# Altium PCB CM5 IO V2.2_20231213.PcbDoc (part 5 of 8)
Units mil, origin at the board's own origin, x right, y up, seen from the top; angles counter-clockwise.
Board outline 6299.61 x 3544.09 mil, 4 copper layers (Top, GND, Power, Bottom), stack 35.4 mil thick; 482 components, 404 nets, 1857 pads, 2731 vias.
Unrouted connection lines stored in the file: 1872.
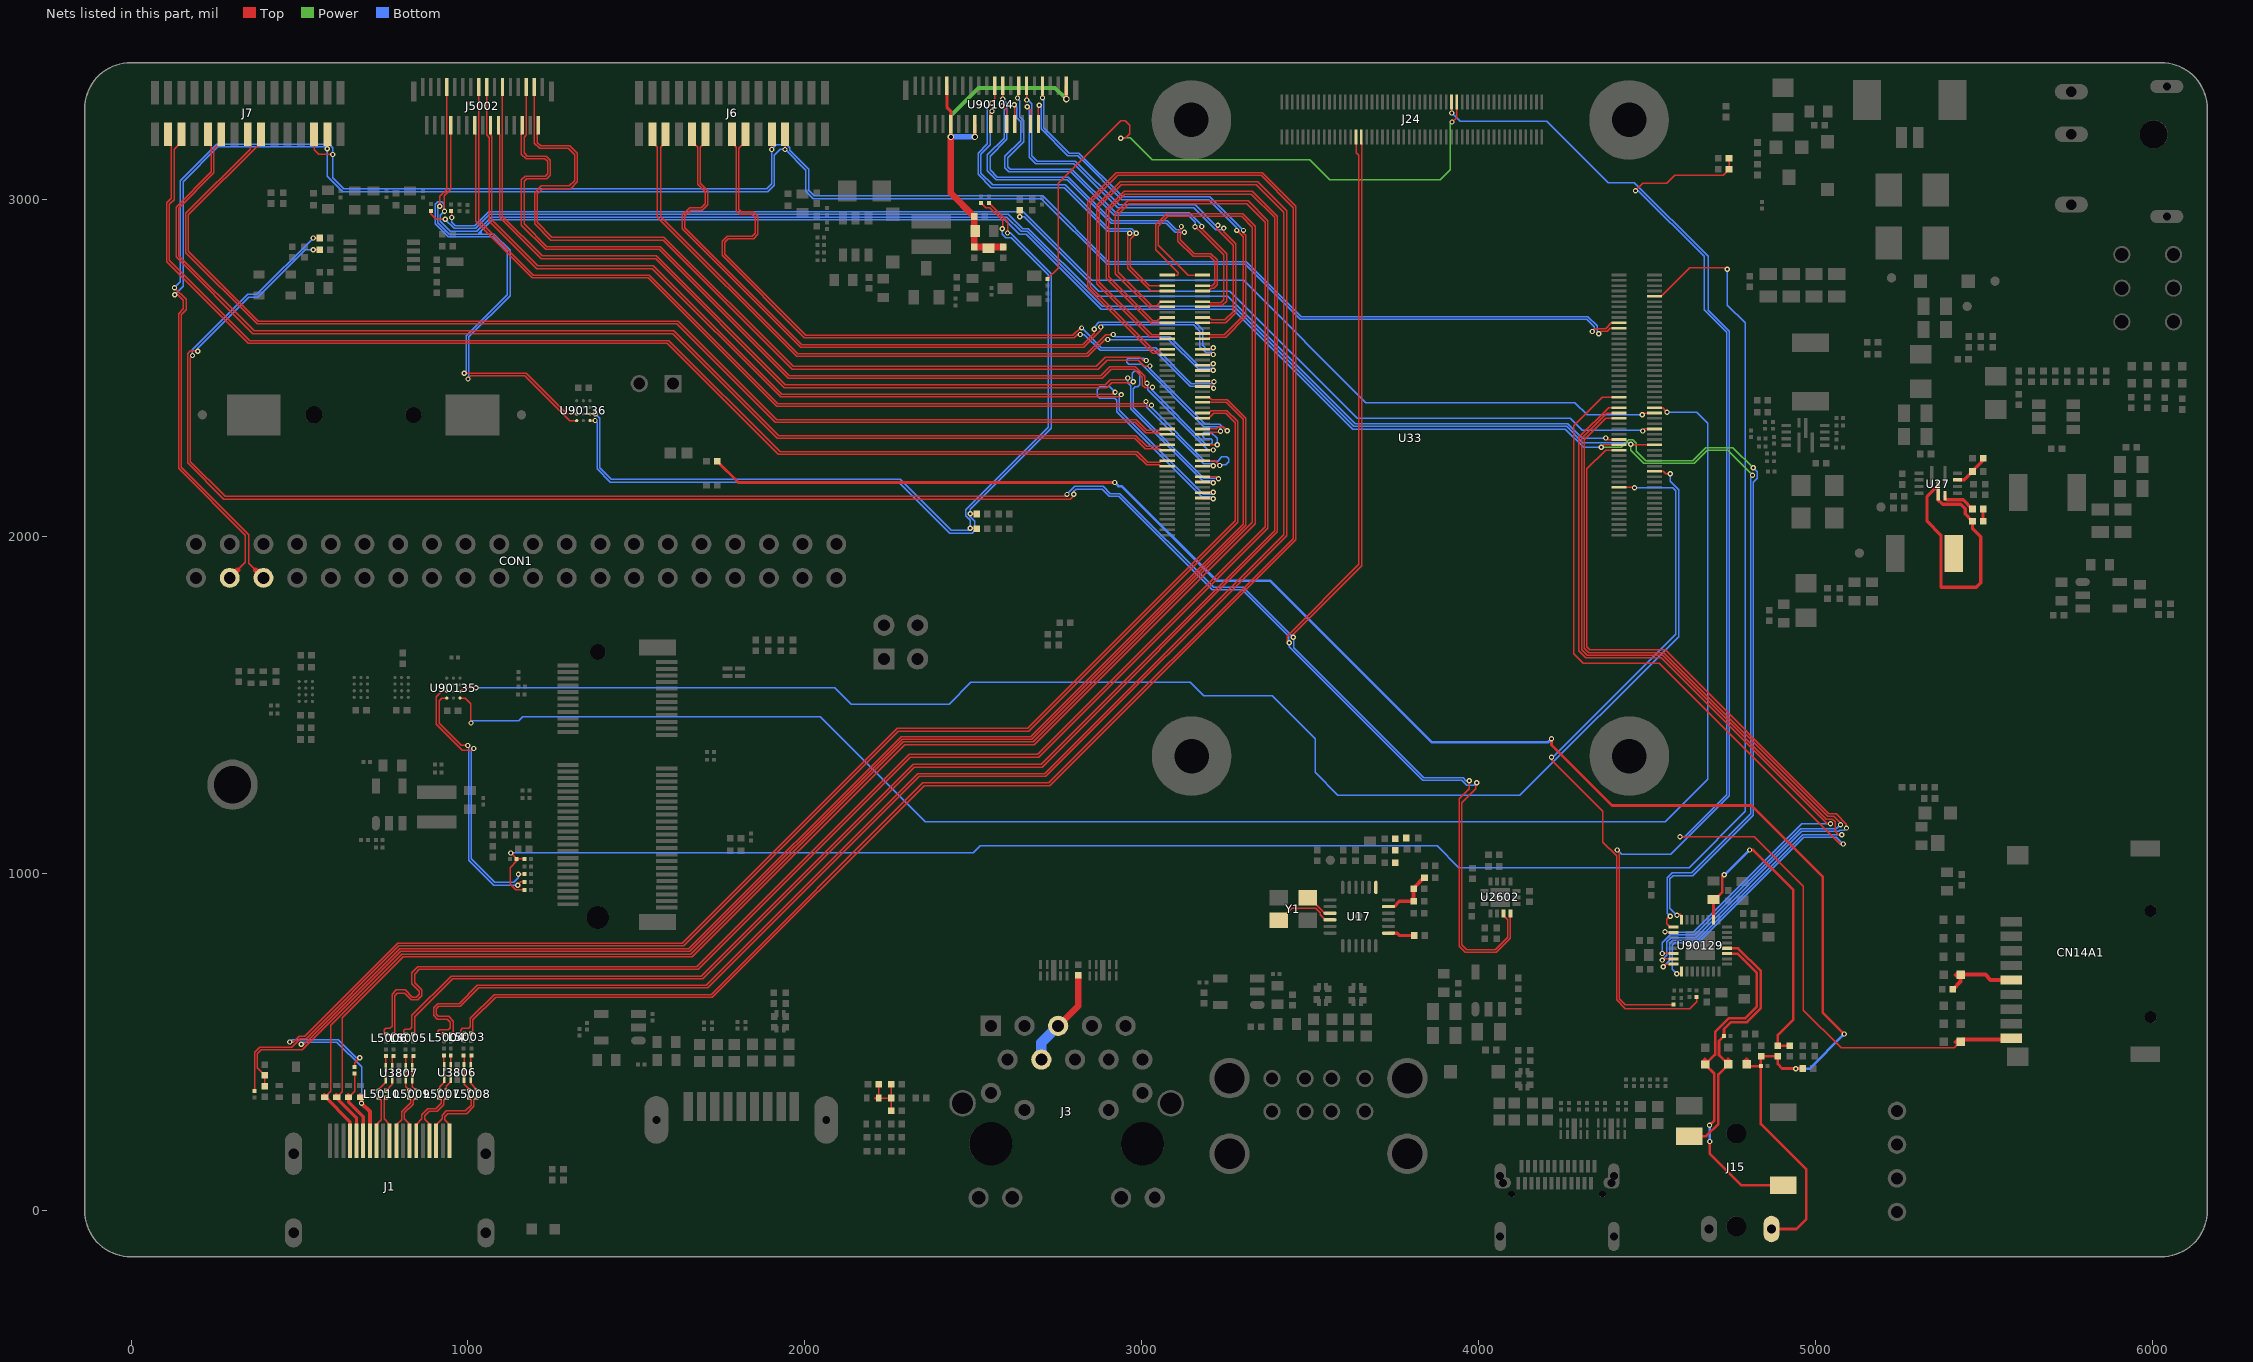
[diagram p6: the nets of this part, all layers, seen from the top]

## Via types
v1: diameter 15.75, hole 7.87, Top to Bottom, 2292 vias
v2: diameter 19.68, hole 11.81, Top to Bottom, 439 vias

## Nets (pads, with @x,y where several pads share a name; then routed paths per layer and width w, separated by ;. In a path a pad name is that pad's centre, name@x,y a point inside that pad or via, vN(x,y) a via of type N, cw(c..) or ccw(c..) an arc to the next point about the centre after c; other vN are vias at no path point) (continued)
HDMI0_SBDP: C90429.2 ED5.1 J1.14 | length 224.1
  Top w3.94: ED5.1@645.67,334.65 663.39,352.36 C90429.2@663.39,405.51
  Top w9.84: ED5.1@645.67,334.65 645.67,320.87 688.98,277.56 J1.14@688.98,206.69
HDMI0_TX0N: L5005.2 R957.1 U33.184 | length 5135.2
  Top w3.94: L5005.2@816.73,521.65 816.73,520.67 R957.1@814.96,520.67 810.04,525.59 810.04,533.46 813.98,537.4 827.76,537.4 833.66,543.31 833.66,577.76 950.79,694.88 1692.91,694.88 2320.87,1322.83 2700.51,1322.83 3393.7,2016.02 3393.7,2945.87 3324.8,3014.76 2949.32,3014.76 2901.57,2967.02 2901.57,2769.68 3032.48,2638.78 3045.28,2638.78 3055.51,2649.02 U33.184@3075.2,2649.02
HDMI0_TX0N_PORT: C90422.2 L5009.2 R95267.1 U3807.2 U3807.9 | length 110.3
  Top w3.94: C90422.2@814.96,457.68 814.96,444.39 U3807.2@814.96,423.72 U3807.9@814.96,389.28 814.96,366.93 L5009.2@826.57,355.31 826.57,355.02 825.34,353.79 825.34,354.33 R95267.1@824.8,354.33
HDMI0_TX0N_PORT_C: J1.9 L5009.3 R95267.2 | length 145.8
  Top w3.94: J1.9@787.41,206.69 787.41,252.96 803.15,268.7 803.15,292.32 829.72,318.9 829.72,330.51 L5009.3@826.57,333.66
HDMI0_TX0P: L5005.1 R956.1 U33.182 | length 5154.5
  Top w3.94: R956.1@837.6,520.67 837.01,520.67 837.01,520.08 835.63,521.46 L5005.1@835.63,521.65 841.54,527.56 841.54,573.82 954.72,687.01 1696.85,687.01 2324.8,1314.96 2703.79,1314.96 3401.57,2012.74 3401.57,2949.8 3327.76,3023.62 2947.04,3023.62 2893.7,2970.28 2893.7,2765.75 3028.54,2630.91 3053.15,2630.91 3055.51,2633.27 U33.182@3075.2,2633.27
HDMI0_TX0P_PORT: C90421.2 L5009.1 R95268.1 U3807.1 U3807.10 | length 108.1
  Top w3.94: C90421.2@837.6,457.68 834.65,454.72 U3807.1@834.65,423.72 U3807.10@834.65,389.28 834.65,366.14 L5009.1@845.47,355.31
HDMI0_TX0P_PORT_C: J1.7 L5009.4 R95268.2 | length 147.8
  Top w3.94: J1.7@826.78,206.69 826.78,254.92 811.02,270.67 811.02,288.39 837.6,314.96 837.6,325.79 L5009.4@845.47,333.66
HDMI0_TX1N: L5004.2 R955.1 U33.178 | length 5328.4
  Top w3.94: L5004.2@928.94,522.64 928.15,521.85 R955.1@928.15,521.65 913.39,521.65 910.43,524.61 910.43,530.51 915.35,535.43 941.73,535.43 947.83,541.54 947.83,558.07 938.98,566.93 908.46,566.93 897.64,577.76 897.64,601.24 909.59,613.19 973.43,613.19 1027.56,667.32 1706.69,667.32 2334.65,1295.28 2711.96,1295.28 3421.26,2004.57 3421.26,2961.61 3339.57,3043.31 2938.89,3043.31 2874.02,2978.43 2874.02,2752.95 3028.54,2598.43 3051.18,2598.43 3054.53,2601.77 U33.178@3075.2,2601.77
HDMI0_TX1N_PORT: C90420.2 L5007.2 R95264.1 U3806.1 U3806.10 | length 113.2
  Top w3.94: R95264.1@914.37,354.33 914.91,354.33 914.91,353.79 916.14,355.02 L5007.2@916.14,355.31 916.14,366.93 929.13,379.92 U3806.1@929.13,391.24 U3806.10@929.13,425.68 928.15,426.67 C90420.2@928.15,459.65
HDMI0_TX1N_PORT_C: J1.6 L5007.3 R95264.2 | length 177.9
  Top w3.94: J1.6@846.46,206.69 846.46,253.94 863.19,270.67 863.19,283.46 880.91,301.18 904.53,301.18 920.28,316.93 920.28,328.74 R95264.2@914.37,334.65 914.91,334.65 914.91,335.19 916.14,333.96 L5007.3@916.14,333.66
HDMI0_TX1P: L5004.1 R954.1 U33.176 | length 5324.7
  Top w3.94: L5004.1@947.83,522.64 R954.1@948.82,521.65 955.71,528.54 955.71,561.33 942.24,574.8 911.73,574.8 905.51,581.02 905.51,597.98 912.85,605.31 977.36,605.31 1031.5,659.45 1711.61,659.45 2339.57,1287.4 2715.24,1287.4 3429.13,2001.29 3429.13,2965.55 3343.5,3051.18 2935.63,3051.18 2866.14,2981.69 2866.14,2749.35 3024.94,2590.55 3051.18,2590.55 3055.71,2586.02 U33.176@3075.2,2586.02
HDMI0_TX1P_PORT: C90427.2 L5007.1 R95263.1 U3806.2 U3806.9 | length 113
  Top w3.94: R95263.1@937.01,354.33 935.04,354.33 L5007.1@935.04,355.31 935.04,367.12 948.82,380.91 U3806.2@948.82,391.24 U3806.9@948.82,425.68 948.82,446.35 ; 948.82,446.36 C90427.2@948.82,459.65
HDMI0_TX1P_PORT_C: J1.4 L5007.4 R95263.2 | length 178.5
  Top w3.94: J1.4@885.83,206.69 885.83,254.92 871.06,269.68 871.06,279.53 884.84,293.31 908.46,293.31 928.15,312.99 928.15,325.79 R95263.2@937.01,334.65 936.42,334.65 936.42,335.24 935.04,333.86 L5007.4@935.04,333.66
HDMI0_TX2N: L5003.2 R953.1 U33.172 | length 5327.5
  Top w3.94: L5003.2@988.98,523.62 988.98,522.64 R953.1@987.2,522.64 987.2,523.62 981.3,523.62 978.35,526.57 978.35,534.45 983.27,539.37 1001.97,539.37 1006.89,544.29 1006.89,568.9 1077.76,639.76 1721.46,639.76 2349.41,1267.72 2723.45,1267.72 3448.82,1993.09 3448.82,2975.39 3353.35,3070.87 2927.47,3070.87 2846.46,2989.85 2846.46,2740.16 3036.42,2550.2 3051.18,2550.2 3055.51,2554.53 U33.172@3075.2,2554.53
HDMI0_TX2N_PORT: C90426.2 L5008.2 R95266.1 U3806.4 U3806.7 | length 114.7
  Top w3.94: C90426.2@987.2,459.65 988.19,458.66 988.19,445.87 U3806.7@988.18,425.68 U3806.4@988.18,391.24 988.18,373.23 1004.72,356.69 L5008.2@1004.72,355.31 1004.72,355.02 1003.49,353.79 1003.49,354.33 R95266.1@1002.95,354.33
HDMI0_TX2N_PORT_C: J1.3 L5008.3 R95266.2 | length 206.9
  Top w3.94: J1.3@905.52,206.69 905.52,252.96 923.23,270.67 923.23,281.5 936.02,294.29 992.13,294.29 1009.84,312.01 1009.84,327.76 R95266.2@1002.95,334.65
HDMI0_TX2P: L5003.1 R952.1 U33.170 | length 5339.2
  Top w3.94: R952.1@1009.84,522.64 1009.25,522.64 1009.25,522.05 1007.87,523.43 L5003.1@1007.87,523.62 1014.76,530.51 1014.76,564.96 1081.69,631.89 1725.39,631.89 2353.35,1259.84 2726.71,1259.84 3456.69,1989.82 3456.69,2979.33 3357.28,3078.74 2924.21,3078.74 2838.58,2993.11 2838.58,2736.22 3032.48,2542.32 3052.17,2542.32 3055.71,2538.78 U33.170@3075.2,2538.78
HDMI0_TX2P_PORT: C90425.2 L5008.1 R95265.1 U3806.5 U3806.6 | length 115
  Top w3.94: C90425.2@1009.84,459.65 1007.87,457.68 U3806.6@1007.87,425.68 U3806.5@1007.87,391.24 1007.87,375.98 1023.62,360.24 L5008.1@1023.62,355.31 1023.62,355.12 1025,353.74 1025,354.33 R95265.1@1025.59,354.33
HDMI0_TX2P_PORT_C: J1.1 L5008.4 R95265.2 | length 205.3
  Top w3.94: J1.1@944.89,206.69 945.87,206.69 945.87,252.95 931.1,267.72 931.1,277.56 939.96,286.42 996.06,286.42 1017.72,308.07 1017.72,327.76 L5008.4@1023.62,333.66
HDMI0_TX3N: L5006.2 R959.1 U33.190 | length 5136.4
  Top w3.94: L5006.2@758.66,521.65 757.87,520.87 R959.1@757.87,520.67 753.94,520.67 751.97,522.64 751.97,535.43 755.91,539.37 767.72,539.37 774.61,546.26 774.61,640.75 787.4,653.54 813.3,653.54 834.95,631.89 846.46,631.89 855.31,640.75 855.31,650.28 833.66,671.94 833.66,704.72 851.38,722.44 1679.13,722.44 2309.06,1352.36 2690.98,1352.36 3366.14,2027.53 3366.14,2932.09 3311.02,2987.2 2960.74,2987.2 2929.13,2955.6 2929.13,2783.46 3028.54,2684.06 3043.31,2684.06 3055.51,2696.26 U33.190@3075.2,2696.26
HDMI0_TX3N_PORT: C90423.2 L5010.2 R95270.1 U3807.5 U3807.6 | length 114.1
  Top w3.94: R95270.1@734.25,354.33 734.79,354.33 734.79,353.79 736.02,355.02 L5010.2@736.02,355.31 736.02,360.04 755.91,379.93 U3807.6@755.91,389.28 U3807.5@755.91,423.72 755.91,456.69 C90423.2@756.89,457.68
HDMI0_TX3N_PORT_C: J1.12 L5010.3 R95270.2 | length 136
  Top w3.94: J1.12@728.35,206.69 728.35,253.94 743.11,268.7 743.11,326.57 L5010.3@736.02,333.66
HDMI0_TX3P: L5006.1 R958.1 U33.188 | length 5151.4
  Top w3.94: R958.1@778.54,520.67 L5006.1@777.56,521.65 782.48,526.57 782.48,636.81 789.71,644.04 811.67,644.04 831.69,624.02 850.39,624.02 863.19,636.81 863.19,653.54 841.54,675.2 841.54,700.79 855.31,714.57 1683.07,714.57 2312.99,1344.49 2694.26,1344.49 3374.02,2024.25 3374.02,2936.02 3314.96,2995.08 2957.47,2995.08 2921.26,2958.86 2921.26,2779.53 3024.61,2676.18 3051.18,2676.18 3055.51,2680.51 U33.188@3075.2,2680.51
HDMI0_TX3P_PORT: C90424.2 L5010.1 R95269.1 U3807.4 U3807.7 | length 117.8
  Top w3.94: C90424.2@778.54,457.68 775.6,454.73 U3807.4@775.6,423.72 U3807.7@775.6,389.28 775.6,373.04 R95269.1@756.89,354.33 ; R95269.1@756.89,354.33 756.3,354.33 756.3,353.74 754.92,355.12 L5010.1@754.92,355.31 R95269.1@756.89,354.33
HDMI0_TX3P_PORT_C: J1.10 L5010.4 R95269.2 | length 142.9
  Top w3.94: J1.10@767.72,206.69 767.72,253.94 750.98,270.67 750.98,328.74 R95269.2@756.89,334.65 ; R95269.2@756.89,334.65 756.3,334.65 756.3,335.24 754.92,333.86 L5010.4@754.92,333.66 R95269.2@756.89,334.65
HDMI0_TX_SBDN_C: C90430.1 U33.147 | length 4104.7
  Top w3.94: C90430.1@367.13,353.35 367.13,468.5 381.89,483.27 476.38,483.27 501.97,508.86 519.38,508.86 794.97,784.45 1639.76,784.45 2276.57,1421.26 2663.68,1421.26 3284.45,2042.03 3284.45,2340.66 3252.08,2373.03 3205.71,2373.03 3198.23,2365.55 U33.147@3179.13,2365.55
HDMI0_TX_SBDP_C: C90429.1 U33.145 | length 4119.6
  Top w3.94: v1(471.46,499.02) 480.99,499.02 498.71,516.73 516.11,516.73 791.71,792.32 1635.83,792.32 2273.62,1430.12 2661.38,1430.12 3276.57,2045.31 3276.57,2337.4 3248.82,2365.16 3213.58,2365.16 3198.23,2349.8 U33.145@3179.13,2349.8 ; C90429.1@663.39,425.2 663.39,437.01 v1(679.13,452.76)
  Bottom w3.94: v1(471.46,499.02) 478.35,505.91 615.16,505.91 668.31,452.76 v1(679.13,452.76)
HDMI_TX0_CEC_PORT: ED9206.1 J1.13 U33.151 | length 4349.1
  Top w3.94: v1(504.92,492.13) 513.78,492.13 797.24,775.59 1655.2,775.59 2285.12,1405.51 2670.24,1405.51 3300.2,2035.47 3300.2,2347.19 3250.33,2397.05 U33.151@3179.13,2397.05
  Top w9.84: ED9206.1@681.1,334.65 ED9206.1@684.06,334.65
  Top w11.81: ED9206.1@684.06,334.65 v1(684.06,316.93) 708.67,292.32 J1.13@708.67,206.69
  Bottom w3.94: v1(504.92,492.13) 510.83,498.03 611.22,498.03 684.06,425.2 v1(684.06,316.93)
HDMI_TX0_HPD_M0: R95282.1 R95615.1 U33.153 | length 4161.5
  Top w3.94: R95282.1@397.15,367.62 R95615.1@397.15,400.1 375,422.24 375,464.57 385.83,475.39 508.55,475.39 800.87,767.72 1658.46,767.72 2288.39,1397.64 2673.5,1397.64 3308.07,2032.21 3308.07,2350.45 3253.01,2405.51 3206.69,2405.51 3199.41,2412.8 U33.153@3179.13,2412.8
HDMI_TX0_SCL_5V: ED3.1 J1.15 U33.200 | length 5131.5
  Top w3.94: ED3.1@610.24,334.65 626.97,351.38 626.97,571.54 807.4,751.97 1666.22,751.97 2296.14,1381.89 2680.02,1381.89 3335.63,2037.5 3335.63,2920.36 3299.29,2956.69 3073.51,2956.69 3040.35,2923.54 3040.35,2849.56 3108.27,2781.65 3108.27,2777.56 3105.71,2775 U33.200@3075.2,2775
  Top w9.84: ED3.1@610.24,334.65 607.28,334.65 669.3,272.63 J1.15@669.3,206.69
HDMI_TX0_SDA_5V: ED2.1 J1.16 U33.199 | length 5140.6
  Top w3.94: ED2.1@574.8,334.65 592.52,352.36 592.52,548.23 804.13,759.84 1661.73,759.84 2291.65,1389.76 2676.76,1389.76 3327.76,2040.76 3327.76,2917.1 3296.03,2948.82 3076.77,2948.82 3048.23,2920.28 3048.23,2863.39 3137.01,2774.61 3178.74,2774.61 U33.199@3179.13,2775
  Top w9.84: ED2.1@574.8,334.65 577.76,334.65 649.61,262.79 J1.16@649.61,206.69
HOST_WAKE_BT_H: R95147.1 R95152.1 R95154.1 U33.91 | length 5833.3
  Top w3.94: v1(1126.97,1060.04) 1127.18,1060.25 1144.88,1042.55 1144.65,1042.55 R95154.1@1144.65,1042.31 ; R95152.1@1167.28,950.77 1141.75,950.77 1125,967.52 1125,1016.53 1144.65,1036.18 R95154.1@1144.65,1042.31 ; R95147.1@1167.28,1042.31 R95154.1@1144.65,1042.31 ; U33.91@4520.47,2712.01 4540.35,2712.01 4625.59,2797.24 4732.28,2797.24 v1(4737.2,2792.32)
  Bottom w3.94: v1(1126.97,1060.04) 2499.38,1060.04 2520.05,1080.71 3875.98,1080.71 3939.96,1016.73 4624.02,1016.73 4790.35,1183.07 4790.35,2632.87 4737.2,2686.02 v1(4737.2,2792.32)
HP_DET_L: J24.36 R90341.2 | length 3619.2
  Top w3.94: J24.36@3918.7,3288.58 3919.29,3288.58 v1(3919.29,3255.91) ; v1(4410.43,1068.9) 4416.34,1062.99 4416.34,627.95 4434.06,610.24 R90341.2@4577.76,610.24
  Bottom w3.94: v1(3919.29,3255.91) 3943.9,3231.3 4201.77,3231.3 4383.67,3049.4 4460.81,3049.4 4680.12,2830.09 4680.12,2671.26 4743.11,2608.27 4743.11,1229.39 4569.82,1056.1 4423.23,1056.1 v1(4410.43,1068.9)
HP_INT: R95573.2 U33.20 | length 2190.1
  Top w3.94: v1(4215.55,1344.49) 4215.55,1335.63 4368.11,1183.07 4368.11,1091.54 4408.46,1051.18 4408.46,624.69 4434.73,598.43 4625.98,598.43 4645.67,618.11 R95573.2@4645.67,632.87 ; U33.20@4415.75,2145.08 4461.61,2145.08 v1(4461.61,2143.7)
  Bottom w3.94: v1(4215.55,1344.49) 4219.37,1344.49 4584.65,1709.77 4584.65,2134.84 4575.79,2143.7 v1(4461.61,2143.7)
HPOL: ED2111.1 J15.3 R90338.2 U90129.20 | length 786
  Top w7.87: J15.3@4624.04,219.67 4674.21,219.67 4710.63,256.09 4710.63,403.15 ED2111.1@4740.16,432.68 4712.6,460.24 4712.6,501.97 R90338.2@4727.36,516.73 4727.36,537.23 4748.2,558.07 4795.28,558.07 4836.61,599.41 4836.61,709.65 4769.07,777.19 U90129.20@4736.4,777.19
HPOR: ED2110.1 J15.6 U90129.19 | length 1016.1
  Top w7.87: v1(4684.06,251.97) 4698.82,266.73 4698.82,404.83 ED2110.1@4671.35,432.3 4671.41,432.24 4700.79,461.61 4700.79,528.54 4742.13,569.88 4790.35,569.88 4824.8,604.33 4824.8,704.36 4767.72,761.44 U90129.19@4736.4,761.44 ; v1(4685.04,203.74) 4685.04,167.32 4778.36,74 J15.6@4903.57,74
  Bottom w7.87: v1(4684.06,251.97) 4685.04,250.98 v1(4685.04,203.74)
I2C4_SCL_M3_WIFI: U33.49 U90135.D3 | length 5189.1
  Top w3.94: U90135.D3@976.38,1519.68 992.13,1519.68 1008.86,1502.95 v1(1008.86,1445.87) ; U33.49@4520.47,2381.3 4544.88,2381.3 v1(4558.07,2368.11)
  Bottom w3.94: v1(1008.86,1445.87) 1014.76,1451.77 1150.17,1451.77 1161.98,1463.58 2045.28,1463.58 2356.3,1152.56 4552.9,1152.56 4679.13,1278.79 4679.13,2334.65 4645.67,2368.11 v1(4558.07,2368.11)
I2C4_SCL_M3_WIFI_E: R95150.1 U90135.D1 | length 747.1
  Top w3.94: U90135.D1@937.01,1519.68 922.24,1519.68 914.37,1511.81 914.37,1444.52 979.95,1378.94 v1(999.02,1378.94) ; v1(1147.64,964.57) 1147.83,965.5 1156.72,974.4 R95150.1@1167.28,974.4
  Bottom w3.94: v1(999.02,1378.94) 1001.97,1375.98 1001.97,1038.39 1075.79,964.57 v1(1147.64,964.57)
I2C4_SDA_M3_WIFI: U33.25 U90135.C3 | length 4603.2
  Top w3.94: U90135.C3@976.38,1539.37 987.2,1550.2 v1(1023.62,1550.2) ; U33.25@4520.47,2192.32 4546.85,2192.32 4554.13,2185.04 v1(4567.91,2185.04)
  Bottom w3.94: v1(1023.62,1550.2) 2088.58,1550.2 2136.81,1501.97 2428.15,1501.97 2492.13,1565.94 3143.7,1565.94 3183.07,1526.57 3386.7,1526.57 3513.78,1399.5 3513.78,1299.21 3581.69,1231.3 4121.85,1231.3 4592.52,1701.97 4592.52,2138.1 4567.91,2162.71 v1(4567.91,2185.04)
I2C4_SDA_M3_WIFI_E: R95149.1 U90135.C1 | length 797.6
  Top w3.94: U90135.C1@937.01,1539.37 922.24,1539.37 906.5,1523.62 906.5,1441.25 983.58,1364.17 1010.83,1364.17 v1(1016.73,1370.08) ; v1(1149.61,997.05) R95149.1@1167.28,997.03
  Bottom w3.94: v1(1016.73,1370.08) 1009.84,1363.19 1009.84,1042.32 1079.72,972.44 1135.83,972.44 1149.61,986.22 v1(1149.61,997.05)
I2C6_SCL_M3: J24.71 R120.2 U2602.6 | length 7452.6
  Top w3.94: v1(198.43,2548.43) 196.85,2550 176.38,2550 168.31,2541.93 168.31,2217.52 275.59,2110.24 2787.4,2110.24 2800,2122.83 v1(2798.03,2124.8) ; v1(540.35,2850.39) R120.2@560.04,2850.39 ; v1(3437.01,1684.06) 3431.1,1689.96 3431.1,1703.74 3643.7,1916.34 3643.7,3129.79 3635.24,3138.25 J24.71@3635.24,3184.65 ; v1(3993.11,1268.7) 3990.16,1265.75 3990.16,1250.26 3949.55,1209.65 3949.55,787.09 3963.14,773.5 4048.68,773.5 4085.19,810.01 4085.19,861.48 4073.45,873.22 U2602.6@4073.45,880.28
  Bottom w3.94: v1(198.43,2548.43) 198.43,2558.35 349.72,2709.65 376.29,2709.65 517.04,2850.39 v1(540.35,2850.39) ; v1(2798.03,2124.8) 2798.03,2132.87 2804.92,2139.76 2881.64,2139.76 2903.29,2118.11 2931.5,2118.11 3209.06,1840.55 3296.94,1840.55 3435.04,1702.45 3435.04,1684.06 v1(3437.01,1684.06) 3437.01,1671.26 3832.68,1275.59 3948.82,1275.59 3963.58,1260.83 3985.24,1260.83 v1(3993.11,1268.7)
I2C6_SDA_M3: J24.69 R95377.2 U2602.7 | length 7402.9
  Top w3.94: v1(182.28,2536.22) 176.18,2530.12 176.18,2221.46 279.13,2118.5 2773.23,2118.5 2778.35,2123.62 2778.35,2124.02 v1(2777.56,2124.02) ; v1(540.35,2884.84) R95377.2@560.04,2884.84 ; v1(3448.82,1699.8) 3448.82,1709.65 3651.57,1912.4 3651.57,3165.55 3650.98,3166.14 J24.69@3650.98,3184.65 ; v1(3971.46,1274.61) 3971.46,1251.24 3941.67,1221.46 3941.67,783.83 3959.89,765.62 4051.98,765.62 4093.14,806.78 U2602.7@4093.14,880.28
  Bottom w3.94: v1(182.28,2536.22) 182.28,2553.35 346.46,2717.52 373.03,2717.52 v1(540.35,2884.84) ; v1(2777.56,2124.02) 2801.18,2147.64 2884.9,2147.64 2906.55,2125.98 2934.76,2125.98 3212.32,1848.43 3300.2,1848.43 v1(3448.82,1699.8) 3450.79,1699.8 3450.79,1668.62 3835.94,1283.46 3952.76,1283.46 3961.61,1274.61 v1(3971.46,1274.61)
I2C7_SCL_M2: CON1.5 J6.5 J7.3 U33.80 | length 6288.1
  Top w3.94: v1(128.94,2737.2) 163.39,2702.76 163.39,2671.54 148.82,2656.97 148.82,2204.84 349.41,2004.25 349.41,1919.89 369.69,1899.61 ; J7.3@543.31,3192.91 543.31,3146.65 557.09,3132.87 v1(598.43,3132.87) ; v1(1901.57,3147.64) J6.5@1901.57,3192.91 ; v1(4355.31,2600.39) 4363.19,2608.27 4380.27,2608.27 4389.52,2617.52 U33.80@4415.75,2617.52
  Top w15.75: 369.69,1899.61 CON1.5@392.94,1876.36
  Bottom w3.94: v1(128.94,2737.2) 146.65,2754.92 146.65,3055.43 254.61,3163.39 588.38,3163.39 598.43,3153.35 v1(598.43,3132.87) 598.43,3063.3 631.21,3030.51 1886.81,3030.51 1901.57,3045.28 v1(1901.57,3147.64) 1915.35,3161.42 1946.65,3161.42 1954.72,3153.35 1954.72,3144.99 2010.83,3088.89 2010.83,3026.88 2027.87,3009.84 2705.03,3009.84 2899.92,2814.96 3309.36,2814.96 3472.75,2651.57 4323.62,2651.57 4350.39,2624.8 4350.39,2605.31 v1(4355.31,2600.39)
I2C7_SDA_M2: CON1.3 J6.4 J7.2 U33.82 | length 6197.1
  Top w3.94: v1(129.92,2716.54) 138.47,2716.54 155.51,2699.49 155.51,2674.8 140.94,2660.24 140.94,2201.57 339.57,2002.95 339.57,1922.99 316.58,1900 ; v1(582.68,3149.61) J7.2@582.68,3192.91 ; v1(1940.94,3147.64) J6.4@1940.94,3192.91 ; v1(4336.61,2607.28) 4345.47,2616.14 4375.98,2616.14 4393.11,2633.27 U33.82@4415.75,2633.27
  Top w15.75: CON1.3@292.94,1876.36 316.58,1900
  Bottom w3.94: v1(129.92,2716.54) 154.53,2741.14 154.53,3052.17 257.87,3155.51 576.77,3155.51 v1(582.68,3149.61) 582.68,3067.91 628.94,3021.65 1889.76,3021.65 1909.45,3041.34 1909.45,3130.91 1926.18,3147.64 v1(1940.94,3147.64) 2002.95,3085.63 2002.95,3023.62 2024.61,3001.97 2701.77,3001.97 2896.65,2807.09 3306.1,2807.09 3469.49,2643.7 4319.88,2643.7 4342.52,2621.06 4342.52,2613.19 v1(4336.61,2607.28)
I2C8_SCL_M2: R95472.1 R95612.2 U90136.B1 | length 2554.3
  Top w3.94: U90136.B1@1361.96,2362.77 1376.95,2362.77 v1(1377.95,2363.78) ; v1(2490.55,2023.23) 2509.84,2023.23 R95612.2@2509.84,2022.64 ; R95472.1@2522.63,2988.19 2535.78,2975.04 2548.27,2975.04 2586.22,2937.09 2586.22,2912.6 v1(2585.83,2912.6)
  Bottom w3.94: v1(1377.95,2363.78) 1390.94,2350.79 1390.94,2203.27 1425.53,2168.68 2282.22,2168.68 2433.58,2017.32 2484.65,2017.32 v1(2490.55,2023.23) 2490.55,2046.85 2476.77,2060.63 2476.77,2078.35 2722.44,2324.02 2722.44,2776.27 2612.49,2886.22 2595.47,2886.22 2585.83,2895.87 v1(2585.83,2912.6)
I2C8_SCL_M2_CAM: J5002.24 U33.35 U90129.1 U90136.B3 | length 7313.9
  Top w3.94: v1(930.12,2964.57) 930.12,3010.83 948.82,3029.53 J5002.24@948.82,3219.5 ; v1(989.17,2483.27) 990.16,2484.25 1172.24,2484.25 1293.72,2362.77 U90136.B3@1322.59,2362.77 ; v1(4450.79,2272.64) 4452.36,2271.06 U33.35@4520.47,2271.06 ; v1(4567.91,872.05) 4565.94,872.05 4557.09,863.19 4557.09,850.39 4567.3,840.18 U90129.1@4576.96,840.18
  Power w3.94: v1(4450.79,2272.64) 4450.79,2254.92 4489.17,2216.54 4638.78,2216.54 4677.17,2254.92 4738.19,2254.92 v1(4812.01,2181.1)
  Bottom w3.94: v1(989.17,2483.27) 995.08,2489.17 995.08,2594.49 1117.13,2716.54 1117.13,2845.47 1073.82,2888.78 941.31,2888.78 902.56,2927.53 902.56,2985.04 910.63,2993.11 922.05,2993.11 930.12,2985.04 v1(930.12,2964.57) 918.31,2952.76 918.31,2934.06 947.83,2904.53 1026.57,2904.53 1068.9,2946.85 2599.41,2946.85 2641.73,2904.53 2659.45,2904.53 2881.89,2682.09 3272.7,2682.09 3628.99,2325.79 4260.15,2325.79 4308.38,2277.56 4445.87,2277.56 v1(4450.79,2272.64) ; v1(4567.91,872.05) 4559.06,880.91 4559.06,986.22 4573.82,1000.98 4631.21,1000.98 4806.1,1175.87 4806.1,2175.2 v1(4812.01,2181.1)
I2C8_SDA_M2: R95471.1 R95609.1 U90136.A1 | length 2541.5
  Top w3.94: U90136.A1@1361.96,2343.08 1362.19,2343.31 v1(1377.17,2343.31) ; v1(2490.55,2066.54) 2509.84,2066.54 R95609.1@2509.84,2065.94 ; R95471.1@2546.26,2988.19 2601.18,2933.26 v1(2601.18,2900)
  Bottom w3.94: v1(1377.17,2343.31) 1383.07,2337.4 1383.07,2199.93 1422.19,2160.8 2278.96,2160.8 2430.31,2009.45 2496.26,2009.45 2504.33,2017.52 2504.33,2044.49 2490.55,2058.27 v1(2490.55,2066.54) 2490.55,2080.71 2730.31,2320.47 2730.31,2779.53 2609.84,2900 v1(2601.18,2900)
I2C8_SDA_M2_CAM: J5002.25 U33.36 U90129.32 U90136.A3 | length 7236.6
  Top w3.94: v1(916.34,2979.33) 916.34,3008.18 937.01,3028.86 J5002.25@937.01,3332.68 ; v1(1000,2466.54) 1000,2467.52 1008.86,2476.38 1168.98,2476.38 1302.28,2343.08 U90136.A3@1322.59,2343.08 ; v1(4363.19,2263.78) 4370.47,2271.06 U33.36@4415.75,2271.06 ; v1(4587.6,875) 4587.6,877.95 4597.44,877.95 4601.56,873.83 U90129.32@4601.56,861.84
  Power w3.94: v1(4363.19,2263.78) 4422.24,2263.78 4444.88,2286.42 4456.5,2286.42 4467.52,2275.39 4467.52,2252.17 4495.28,2224.41 4634.84,2224.41 4673.23,2262.8 4753.94,2262.8 v1(4813.98,2202.76)
  Bottom w3.94: v1(916.34,2979.33) 915.35,2979.33 910.43,2974.41 910.43,2930.79 944.57,2896.65 1029.84,2896.65 ; v1(1000,2466.54) 1002.95,2466.54 1002.95,2591.23 1125,2713.27 1125,2848.73 1077.08,2896.65 1042.32,2896.65 ; v1(4363.19,2263.78) 4311.02,2263.78 4256.89,2317.91 3625.73,2317.91 3269.43,2674.21 2878.63,2674.21 2656.38,2896.46 2636.02,2896.46 2593.5,2938.98 1072.16,2938.98 1039.37,2906.19 ; v1(4587.6,875) 4566.93,895.67 4566.93,982.96 4577.08,993.11 4634.48,993.11 4813.98,1172.61 4813.98,2160.43 4825.79,2172.24 4825.79,2190.94 v1(4813.98,2202.76) ; 1029.84,2896.65 1042.32,2896.65 ; 1029.84,2896.65 1033.77,2900.59 ; 1033.77,2900.59 1033.77,2899.61 1039.37,2899.61 ; 1033.77,2900.59 1039.37,2906.19 ; 1039.37,2899.61 1039.37,2906.19 ; 1039.37,2899.61 1042.32,2896.65
I2S0_LRCK_TX: U33.48 U90129.8 | length 2540.2
  Top w3.94: U33.48@4415.75,2365.55 4379.92,2365.55 4304.53,2290.16 4304.53,1663.39 4321.26,1646.65 4544.85,1646.65 5031.07,1160.43 5049.01,1160.43 5057.09,1152.36 5057.09,1124.02 5066.93,1114.17 v1(5076.77,1114.17) ; v1(4547.24,722.44) 4554.75,729.95 U90129.8@4576.96,729.95
  Bottom w3.94: v1(4547.24,722.44) 4565.94,741.14 4565.94,792.32 4574.8,801.18 4647.64,801.18 4960.63,1114.17 v1(5076.77,1114.17)
I2S0_MCLK: U33.50 U90129.2 | length 2399.9
  Top w3.94: U33.50@4415.75,2381.3 4384.53,2381.3 4296.65,2293.42 4296.65,2273.62 4296.65,1659.45 4317.32,1638.78 4541.59,1638.78 5033.72,1146.65 v1(5043.31,1146.65) ; v1(4552.17,825.79) 4552.17,824.8 4552.53,824.44 U90129.2@4576.96,824.44
  Bottom w3.94: v1(4552.17,825.79) 4552.17,824.8 4635.83,824.8 4957.68,1146.65 v1(5043.31,1146.65)
I2S0_SCLK_TX: U33.46 U90129.6 | length 2466.8
  Top w3.94: U33.46@4415.75,2349.8 4375.98,2349.8 4312.4,2286.22 4312.4,1667.32 4325.2,1654.53 4548.23,1654.53 5034.45,1168.31 5053.15,1168.31 5070.87,1150.59 5070.87,1145.67 v1(5072.83,1143.7) ; v1(4544.29,761.81) 4576.59,761.81 U90129.6@4576.96,761.44
  Bottom w3.94: v1(4544.29,761.81) 4544.29,793.31 4567.91,816.93 4639.76,816.93 4954.72,1131.89 5061.02,1131.89 v1(5072.83,1143.7)
I2S0_SDI0: U33.54 U90129.9 | length 2638.1
  Top w3.94: U33.54@4415.75,2412.8 4366.54,2412.8 4280.91,2327.17 4280.91,1651.57 4309.45,1623.03 4535.07,1623.03 5071.48,1086.61 v1(5080.71,1086.61) ; v1(4586.61,701.77) 4601.56,701.77 U90129.9@4601.56,708.29
  Bottom w3.94: v1(4586.61,701.77) 4573.82,714.57 4573.82,785.43 4581.69,793.31 4651.57,793.31 4964.57,1106.3 5061.02,1106.3 v1(5080.71,1086.61)
I2S0_SDO0: U33.34 U90129.7 | length 2412.7
  Top w3.94: U33.34@4415.75,2255.31 4375.98,2255.31 4320.28,2199.61 4320.28,1671.26 4329.13,1662.4 4552.17,1662.4 5038.39,1176.18 5059.84,1176.18 5090.55,1145.47 v1(5090.55,1133.86) ; v1(4544.29,742.13) 4547.86,745.7 U90129.7@4576.96,745.7
  Bottom w3.94: v1(4544.29,742.13) 4558.07,755.91 4558.07,795.95 4571.17,809.06 4643.7,809.06 4958.66,1124.02 5067.13,1124.02 5071.06,1127.95 5084.65,1127.95 v1(5090.55,1133.86)
LCD1_3V3: C2335.1 C90750.1 C90751.1 C90772.1 R95530.2 U90104.1 U90104.24 U90104.30 U90104.31 | length 1208.1
  Top w3.94: v2(2433.07,3185.04) v2@2433.07,3187.99
  Top w9.84: U90104.31@2421.26,3336.61 2421.26,3273.62 2433.07,3261.81 U90104.30@2433.07,3223.43 v2@2433.07,3187.99 ; v2(2503.94,3185.04) U90104.24@2503.94,3223.43 ; v2(2775.59,3297.24) U90104.1@2775.59,3336.61
  Top w19.68: v2(2433.07,3185.04) 2433.07,3017.71 C90751.1@2501.97,2948.82 C90750.1@2501.97,2905.51 ; C90750.1@2504.92,2905.51 C90750.1@2501.97,2905.51 ; C2335.1@2545.27,2854.33 C2335.1@2545.27,2858.27 ; R95530.2@2588.58,2858.27 C2335.1@2545.27,2858.27 ; C90750.1@2501.97,2905.51 C90772.1@2501.97,2858.27 C2335.1@2545.27,2858.27
  Power w11.81: v2(2433.07,3185.04) 2433.07,3249.02 2514.76,3330.71 2742.13,3330.71 v2(2775.59,3297.24)
  Bottom w15.75: v2(2433.07,3185.04) v2(2503.94,3185.04)
LCD_PWREN_H: J24.34 R95042.1 | length 1902.2
  Top w3.94: R95042.1@2719.49,2763.78 2750.98,2795.28 2750.98,3046.82 2937.43,3233.27 2950.59,3233.27 2963.58,3220.27 2963.58,3194.1 2950.59,3181.1 v1(2937.01,3181.1) ; v1(3920.28,3229.33) 3934.06,3242.13 3934.45,3242.52 J24.34@3934.45,3288.58
  Power w3.94: v1(2937.01,3181.1) 2937.99,3182.09 2965.66,3182.09 3030.62,3117.13 3497.3,3117.13 3557.34,3057.09 3884.84,3057.09 3915.35,3087.6 3915.35,3223.43 3920.77,3228.84 v1(3920.28,3229.33)
LCD_RESET_L: R95468.1 U33.41 | length 2168.3
  Top w3.94: v1(2637.8,2947.83) R95468.1@2637.8,2967.52 ; v1(4486.22,2312.01) 4492.52,2318.31 U33.41@4520.47,2318.31
  Bottom w3.94: v1(2637.8,2947.83) 2650.59,2947.83 2871.06,2727.36 3260.83,2727.36 3638.78,2349.41 4270.67,2349.41 4306.1,2313.98 4484.25,2313.98 v1(4486.22,2312.01)
MIC_IN2P: C560.2 C90084.1 ED2109.1 J15.5 R7120.1 R7313.1 R7314.2 | length 5345.9
  Top w7.87: R7120.1@1739.17,2222.44 1802.17,2159.45 v1(2919.29,2159.45) ; v1(4215.55,1398.62) 4215.55,1380.68 4395.44,1200.79 4809.06,1200.79 5020.67,989.17 5020.67,585.63 v1(5083.66,522.64) ; ED2109.1@4795.28,432.68 4795.28,427.17 4835.63,427.17 C90084.1@4836.61,428.15 ; J15.5@4868.14,-55.92 4942.11,-55.92 4971.46,-26.57 4971.46,121.06 4836.61,255.91 C90084.1@4836.61,428.15 ; v1(4939.96,419.29) v1@4939.96,420.28 ; R7314.2@4960.63,420.28 v1@4939.96,420.28 ; C90084.1@4836.61,428.15 4836.61,456.69 C560.2@4837.6,456.69 R7313.1@4886.81,456.69 4886.81,433.07 4899.61,420.28 v1@4939.96,420.28
  Bottom w7.87: v1(2919.29,2159.45) 2930.12,2148.62 2939.96,2148.62 3220.47,1868.11 3380.34,1868.11 3859.67,1388.78 4205.71,1388.78 v1(4215.55,1398.62) ; v1(4939.96,419.29) 4980.31,419.29 v1(5083.66,522.64)
MICBIAS1: C562.1 C7320.1 R7313.2 U90129.26 | length 950.1
  Top w7.87: U90129.26@4696.05,861.84 C562.1@4696.05,921.88 4699.99,921.88 4722.44,944.33 4722.44,989.17 v1(4728.35,995.08) ; v1(4803.15,1068.9) 4813.92,1068.9 4933.07,949.75 4933.07,566 4886.81,519.74 R7313.2@4886.81,488.19 C7320.1@4922.24,488.19
  Bottom w7.87: v1(4728.35,995.08) 4728.84,994.59 v1(4803.15,1068.9)
MIPI_CAM2_PDN_L: R814.1 U33.47 | length 3877.4
  Top w3.94: R814.1@949.8,2964.57 951.77,2964.57 v1(951.77,2945.87) ; v1(4484.25,2360.24) 4484.25,2361.91 4487.89,2365.55 U33.47@4520.47,2365.55
  Bottom w3.94: v1(951.77,2945.87) 951.77,2932.09 962.6,2921.26 1019.69,2921.26 1061.02,2962.6 2647.33,2962.6 2851.07,2758.86 3302.17,2758.86 3664.37,2396.65 4284.45,2396.65 4320.87,2360.24 v1(4484.25,2360.24)
MIPI_CAM2_RST_L: R95580.1 U33.38 | length 3847.5
  Top w3.94: R95580.1@889.76,2965.55 889.76,2956.69 905.51,2940.94 v1(932.09,2940.94) ; v1(4375.98,2291.34) 4380.51,2286.81 U33.38@4415.75,2286.81
  Bottom w3.94: v1(932.09,2940.94) 931.59,2940.45 958.66,2913.39 1023.62,2913.39 1064.96,2954.72 2603.35,2954.72 2645.67,2912.4 2663.08,2912.4 2863.86,2711.61 3254.3,2711.61 3632.26,2333.66 4263.78,2333.66 4306.1,2291.34 v1(4375.98,2291.34)
MIPI_CSI0_RX_CLK0N: J7.8 U33.140 | length 3569.4
  Top w3.94: J7.8@346.46,3192.91 346.46,3169.29 353.35,3162.4 353.35,3148.62 162.4,2957.68 162.4,2841.54 374.02,2629.92 1620.08,2629.92 1912.4,2337.6 2980.31,2337.6 3010.83,2307.09 3051.18,2307.09 3055.71,2302.56 U33.140@3075.2,2302.56
MIPI_CSI0_RX_CLK0P: J7.7 U33.142 | length 3563.1
  Top w3.94: J7.7@385.83,3192.91 385.83,3169.78 170.28,2954.23 170.28,2844.98 377.46,2637.8 1624.02,2637.8 1916.34,2345.47 2983.58,2345.47 3014.09,2314.96 3052.17,2314.96 3055.51,2318.31 U33.142@3075.2,2318.31
MIPI_CSI0_RX_D0N: J7.14 U33.128 | length 3608
  Top w3.94: J7.14@110.24,3192.91 110.24,3169.29 120.08,3159.45 120.08,3002.95 106.3,2989.17 106.3,2814.96 348.43,2572.83 1591.54,2572.83 1921.26,2243.11 2982.28,2243.11 3013.78,2211.61 3051.18,2211.61 3054.72,2208.07 U33.128@3075.2,2208.07
MIPI_CSI0_RX_D0P: J7.13 U33.130 | length 3599.8
  Top w3.94: J7.13@149.61,3192.91 149.61,3170.28 127.95,3148.62 127.95,2998.76 114.17,2984.98 114.17,2818.9 352.36,2580.71 1596.46,2580.71 1926.18,2250.98 2985.54,2250.98 3017.04,2219.49 3052.17,2219.49 3056.5,2223.82 U33.130@3075.2,2223.82
MIPI_CSI0_RX_D1N: J7.11 U33.134 | length 3590.3
  Top w3.94: J7.11@228.35,3192.91 228.35,3169.29 238.19,3159.45 238.19,3081.16 133.86,2976.83 133.86,2828.74 361.22,2601.38 1607.28,2601.38 1918.31,2290.35 2978.88,2290.35 3010.38,2258.86 3052.17,2258.86 3055.71,2255.31 U33.134@3075.2,2255.31
MIPI_CSI0_RX_D1P: J7.10 U33.136 | length 3582.1
  Top w3.94: J7.10@267.72,3192.91 267.72,3170.28 246.06,3148.62 246.06,3077.9 141.73,2973.57 141.73,2832.68 365.16,2609.25 1611.22,2609.25 1922.24,2298.23 2982.14,2298.23 3013.64,2266.73 3051.18,2266.73 3055.51,2271.06 U33.136@3075.2,2271.06
MIPI_DPHY0_RX_CLKN: J5002.17 U33.127 | length 2923.4
  Top w3.94: J5002.17@1031.49,3332.68 1031.49,2937.01 1193.89,2774.61 1538.46,2774.61 1919.37,2393.7 3005.91,2393.7 v1(3011.81,2399.61) ; U33.127@3179.13,2208.07 3179.13,2208.66 v1(3211.61,2208.66)
  Bottom w3.94: v1(3011.81,2399.61) 3014.76,2396.65 3014.76,2383.07 3183.27,2214.57 3205.71,2214.57 v1(3211.61,2208.66)
MIPI_DPHY0_RX_CLKP: J5002.18 U33.129 | length 2928
  Top w3.94: J5002.18@1019.68,3219.5 1019.68,3195.87 1022.64,3192.91 1022.64,2934.06 1189.96,2766.73 1535.2,2766.73 1916.11,2385.83 3025.59,2385.83 v1(3028.54,2388.78) ; U33.129@3179.13,2223.82 3217.13,2223.82 v1(3231.3,2209.65)
  Bottom w3.94: v1(3028.54,2388.78) 3028.54,2380.91 3187.01,2222.44 3224.41,2222.44 3237.2,2235.24 3251.97,2235.24 3256.89,2230.31 3256.89,2220.47 3249.02,2212.6 3234.25,2212.6 v1(3231.3,2209.65)
MIPI_DPHY0_RX_D0N: J5002.14 U33.115 | length 2954.4
  Top w3.94: J5002.14@1066.93,3219.5 1066.93,3190.94 1070.87,3187.01 1070.87,2938.98 1207.68,2802.17 1549.88,2802.17 1930.78,2421.26 2914.37,2421.26 v1(2920.28,2427.17) ; U33.115@3179.13,2113.58 3179.13,2111.61 3199.61,2111.61 v1(3211.61,2111.22)
  Bottom w3.94: v1(2920.28,2427.17) 2904.53,2442.91 2875,2442.91 2867.13,2435.04 2867.13,2417.32 2875,2409.45 2919.29,2409.45 2925.2,2403.54 2925.2,2370.08 3178.15,2117.13 3205.71,2117.13 v1(3211.61,2111.22)
MIPI_DPHY0_RX_D0P: J5002.15 U33.117 | length 2963.7
  Top w3.94: J5002.15@1056.1,3332.68 J5002.15@1055.12,3332.68 1055.12,3190.94 1062.99,3183.08 1062.99,2935.04 1203.74,2794.29 1546.62,2794.29 1927.52,2413.39 2932.09,2413.39 v1(2938.98,2420.28) ; U33.117@3179.13,2129.33 3179.13,2130.91 v1(3211.61,2130.91)
  Bottom w3.94: v1(2938.98,2420.28) 2933.07,2414.37 2933.07,2374.02 3182.09,2125 3205.71,2125 v1(3211.61,2130.91)
MIPI_DPHY0_RX_D1N: J5002.11 U33.121 | length 2922.6
  Top w3.94: J5002.11@1102.36,3332.68 1102.36,2949.8 1220.47,2831.69 1559.33,2831.69 1942.2,2448.82 2891.73,2448.82 2906.5,2463.58 2957.68,2463.58 v1(2957.68,2469.49) ; U33.121@3179.13,2160.83 3209.25,2160.83 v1(3211.61,2158.46)
  Bottom w3.94: v1(2957.68,2469.49) 2957.68,2455.71 2966.54,2446.85 2966.54,2377.64 3179.81,2164.37 3205.71,2164.37 v1(3211.61,2158.46)
MIPI_DPHY0_RX_D1P: J5002.12 U33.123 | length 2929.8
  Top w3.94: J5002.12@1090.55,3219.5 1090.55,3195.87 1094.49,3191.93 1094.49,2945.87 1217.52,2822.83 1557.05,2822.83 1938.94,2440.94 2895.67,2440.94 2910.43,2455.71 2971.46,2455.71 v1(2974.41,2458.66) ; U33.123@3179.13,2176.57 3221.06,2176.57 v1(3227.36,2170.28)
  Bottom w3.94: v1(2974.41,2458.66) 2971.46,2461.61 2971.46,2483.27 2977.36,2489.17 2987.2,2489.17 2993.11,2483.27 2993.11,2448.82 2988.19,2443.9 2980.31,2443.9 2974.41,2437.99 2974.41,2380.91 3183.07,2172.24 3225.39,2172.24 v1(3227.36,2170.28)
MIPI_DPHY0_RX_D2N: J5002.5 U33.133 | length 2937.1
  Top w3.94: J5002.5@1173.23,3332.68 1173.23,3190.95 1166.34,3184.06 1166.34,3137.8 1176.18,3127.95 1232.28,3127.95 1244.09,3116.14 1244.09,3071.85 1233.27,3061.02 1174.21,3061.02 1166.34,3053.15 1166.34,2927.16 1234.25,2859.25 1570.74,2859.25 1953.61,2476.38 2877.95,2476.38 2904.53,2502.95 2980.31,2502.95 3008.86,2474.41 3008.86,2459.65 v1(3014.76,2453.74) ; U33.133@3179.13,2255.31 3179.13,2255.91 v1(3211.61,2255.91)
  Bottom w3.94: v1(3014.76,2453.74) 3017.72,2450.79 3017.72,2434.06 3195.87,2255.91 v1(3211.61,2255.91)
MIPI_DPHY0_RX_D2P: J5002.6 U33.135 | length 2960.7
  Top w3.94: J5002.6@1161.42,3219.5 1161.42,3195.87 1158.46,3192.91 1158.46,3133.86 1172.24,3120.08 1228.35,3120.08 1236.22,3112.2 1236.22,3075.79 1229.33,3068.9 1170.28,3068.9 1158.46,3057.09 1158.46,2923.23 1230.31,2851.38 1567.48,2851.38 1950.35,2468.5 2881.89,2468.5 2908.46,2495.08 2977.05,2495.08 3000.98,2471.15 3000.98,2448.03 3009.06,2439.96 3029.53,2439.96 v1(3031.5,2441.93) ; U33.135@3179.13,2271.06 3223.43,2271.06 v1(3223.43,2271.65)
  Bottom w3.94: v1(3031.5,2441.93) 3028.54,2438.98 3028.54,2434.36 3189.96,2272.95 3203.43,2272.95 3208.35,2277.87 3208.35,2284.76 3203.43,2289.68 3186.7,2289.68 3180.12,2296.26 3180.12,2304.13 3185.04,2309.06 3204.42,2309.06 3223.43,2290.05 v1(3223.43,2271.65)
MIPI_DPHY0_RX_D3N: J5002.2 U33.139 | length 2983.2
  Top w3.94: J5002.2@1208.66,3219.5 1208.66,3195.87 1205.71,3192.91 1205.71,3168.31 1215.55,3158.46 1302.17,3158.46 1324.8,3135.83 1324.8,3051.18 1305.12,3031.5 1221.46,3031.5 1205.71,3015.75 1205.71,2931.1 1249.01,2887.8 1581.17,2887.8 1965.03,2503.94 2864.17,2503.94 2890.75,2530.51 2993.11,2530.51 3001.97,2521.65 v1(3012.8,2521.65) ; U33.139@3179.13,2302.56 3200.2,2302.56 3206.69,2309.06 3231.3,2309.06 v1(3233.27,2311.02)
  Bottom w3.94: v1(3012.8,2521.65) 3005.91,2528.54 2959.65,2528.54 2954.72,2523.62 2954.72,2515.75 2960.63,2509.84 2999.02,2509.84 3184.06,2324.8 3227.36,2324.8 3233.27,2318.9 v1(3233.27,2311.02)
MIPI_DPHY0_RX_D3P: J5002.3 U33.141 | length 3025.2
  Top w3.94: J5002.3@1198.82,3332.68 J5002.3@1196.85,3332.68 1196.85,3166.03 1212.29,3150.59 1298.23,3150.59 1316.25,3132.57 1316.25,3054.44 1301.18,3039.37 1217.52,3039.37 1197.83,3019.68 1197.83,2927.16 1246.06,2878.94 1578.89,2878.94 1961.77,2496.06 2869.8,2496.06 2896.37,2522.64 2989.17,2522.64 3006.89,2504.92 v1(3023.62,2504.92) ; U33.141@3179.13,2318.31 3220.87,2318.31 3227.36,2324.8 3241.14,2324.8 v1(3252.95,2312.99)
  Bottom w3.94: v1(3023.62,2504.92) 3021.65,2504.92 3021.65,2499.02 3187.99,2332.68 3231.1,2332.68 v1@3247.05,2316.73 ; v1@3247.05,2316.71 v1(3252.95,2312.99)
MIPI_DPHY0_TX_CLKN: J6.11 U33.169 | length 2195.5
  Top w3.94: J6.11@1665.35,3192.91 1665.35,3169.29 1681.1,3153.54 1681.1,3044.29 1703.74,3021.65 1703.74,2987.2 1691.93,2975.39 1657.48,2975.39 1635.83,2953.74 1635.83,2912.2 1987.01,2561.02 2827.48,2561.02 2877.95,2611.5 v1(2877.95,2621.06) ; U33.169@3179.13,2538.78 3179.13,2539.37 v1(3211.61,2539.37)
  Bottom w3.94: v1(2877.95,2621.06) 2883.86,2626.97 3153.54,2626.97 3172.24,2608.27 3172.24,2562.01 3188.98,2545.28 3205.71,2545.28 v1(3211.61,2539.37)
MIPI_DPHY0_TX_CLKP: J6.10 U33.171 | length 2189.1
  Top w3.94: J6.10@1704.72,3192.91 1704.72,3169.29 1688.98,3153.54 1688.98,3047.55 1711.61,3024.91 1711.61,2983.27 1695.87,2967.52 1660.74,2967.52 1643.7,2950.48 1643.7,2915.46 1990.27,2568.9 2824.21,2568.9 2858.27,2602.95 v1(2858.27,2614.17) ; U33.171@3179.13,2554.53 3207.09,2554.53 v1(3211.61,2559.06)
  Bottom w3.94: v1(2858.27,2614.17) 2859.25,2615.16 2859.25,2621.85 2872.25,2634.84 3157.48,2634.84 3180.12,2612.2 3180.12,2565.94 3192.91,2553.15 3205.71,2553.15 v1(3211.61,2559.06)
MIPI_DPHY0_TX_D0N: J6.8 U33.157 | length 2158.9
  Top w3.94: J6.8@1783.46,3192.91 1783.46,3167.32 1796.26,3154.53 1796.26,2966.54 1807.09,2955.71 1842.52,2955.71 1852.36,2945.87 1852.36,2899.61 1843.5,2890.75 1769.69,2890.75 1753.94,2875 1753.94,2833.07 1998.42,2588.58 2798.62,2588.58 2808.46,2598.43 v1(2816.93,2598.43) ; U33.157@3179.13,2444.29 3207.28,2444.29 v1(3212.6,2438.98)
  Bottom w3.94: v1(2816.93,2598.43) 2828.74,2598.43 2875.98,2551.18 3036.42,2551.18 3142.72,2444.88 3206.69,2444.88 v1(3212.6,2438.98)
MIPI_DPHY0_TX_D0P: J6.7 U33.159 | length 2159.9
  Top w3.94: J6.7@1822.83,3192.91 1822.83,3169.29 1804.13,3150.59 1804.13,2969.8 1810.35,2963.58 1846.46,2963.58 1860.24,2949.8 1860.24,2895.67 1847.44,2882.87 1772.95,2882.87 1761.81,2871.74 1761.81,2836.61 2001.97,2596.46 2795.28,2596.46 2817.98,2619.16 2819.81,2619.16 v1(2820.87,2618.11) ; U33.159@3179.13,2460.04 3212.2,2460.04 v1(3213.58,2458.66)
  Bottom w3.94: v1(2820.87,2618.11) 2879.92,2559.06 3040.35,2559.06 3146.65,2452.76 3207.68,2452.76 v1(3213.58,2458.66)
MIPI_DPHY0_TX_D1N: J6.14 U33.163 | length 2164.7
  Top w3.94: J6.14@1547.24,3192.91 1547.24,3168.31 1562.01,3153.54 1562.01,2947.05 1975.59,2533.46 2839.57,2533.46 2889.76,2583.66 v1(2898.62,2583.66) ; U33.163@3179.13,2491.54 3211.61,2491.54 v1(3211.61,2492.13)
  Bottom w3.94: v1(2898.62,2583.66) 3079.72,2583.66 3165.35,2498.03 3205.71,2498.03 v1(3211.61,2492.13)
MIPI_DPHY0_TX_D1P: J6.13 U33.165 | length 2157.8
  Top w3.94: J6.13@1586.61,3192.91 1586.61,3168.31 1571.85,3153.54 1571.85,2948.34 1978.85,2541.34 2835.63,2541.34 2892.72,2598.43 v1(2914.37,2598.43) ; U33.165@3179.13,2507.28 3207.09,2507.28 v1(3211.61,2511.81)
  Bottom w3.94: v1(2914.37,2598.43) 2921.26,2591.54 3082.99,2591.54 3168.62,2505.91 3205.71,2505.91 v1(3211.61,2511.81)
MIPI_DPHY1_TX_CLKN: U33.187 U90104.13 | length 1251.5
  Top w3.94: v1(2630.91,3300.2) 2633.86,3303.15 U90104.13@2633.86,3336.61 ; v1(3177.17,2919.29) 3177.17,2912.4 3250.98,2838.58 3250.98,2697.83 3238.19,2685.04 3202.76,2685.04 3198.23,2680.51 U33.187@3179.13,2680.51
  Bottom w3.94: v1(2630.91,3300.2) 2629.85,3299.14 2636.81,3292.18 2636.81,3244.46 2648.62,3232.65 2648.62,3170.28 2601.38,3123.03 2601.38,3096.77 2608.58,3089.57 2791.71,3089.57 2921.63,2959.65 3140.75,2959.65 3177.17,2923.23 v1(3177.17,2919.29)
MIPI_DPHY1_TX_CLKP: U33.189 U90104.14 | length 1237.9
  Top w3.94: v1(2621.06,3280.51) 2622.05,3279.53 U90104.14@2622.05,3223.43 ; v1(3157.48,2918.31) 3180.12,2897.64 3243.11,2834.65 3243.11,2701.77 3234.25,2692.91 3202.76,2692.91 3199.41,2696.26 U33.189@3179.13,2696.26
  Bottom w3.94: v1(2621.06,3280.51) 2628.94,3272.64 2628.94,3241.2 2640.75,3229.39 2640.75,3174.21 2593.5,3126.97 2593.5,3093.5 2605.31,3081.69 2788.44,3081.69 2918.37,2951.77 3136.81,2951.77 3157.48,2931.1 v1(3157.48,2918.31)
MIPI_DPHY1_TX_D0N: U33.175 U90104.7 | length 1260.9
  Top w3.94: v1(2704.72,3301.18) U90104.7@2704.72,3336.61 ; U33.175@3179.13,2586.02 3197.64,2586.02 3202.17,2590.55 3248.03,2590.55 3308.07,2650.59 3308.07,2892.72 3301.18,2899.61 v1(3301.18,2907.48)
  Bottom w3.94: v1(2704.72,3301.18) 2705.71,3301.18 2708.66,3298.23 2708.66,3211.92 2783.77,3136.81 2812.99,3136.81 2942.91,3006.89 3201.77,3006.89 v1(3301.18,2907.48)
MIPI_DPHY1_TX_D0P: U33.177 U90104.8 | length 1244.7
  Top w3.94: U90104.8@2692.91,3223.43 2692.91,3276.57 v1(2694.88,3278.54) ; U33.177@3179.13,2601.77 3199.8,2601.77 3203.15,2598.43 3244.09,2598.43 3300.2,2654.53 3300.2,2888.78 v1(3281.5,2907.48)
  Bottom w3.94: v1(2694.88,3278.54) 2700.79,3272.64 2700.79,3208.66 2780.51,3128.94 2809.36,3128.94 2821.84,3116.47 2822.2,3116.47 2939.65,2999.02 3197.83,2999.02 3281.5,2915.35 v1(3281.5,2907.48)
MIPI_DPHY1_TX_D1N: U33.181 U90104.10 | length 1254.3
  Top w3.94: v1(2659.45,3274.61) 2669.29,3264.76 U90104.10@2669.29,3223.43 ; U33.181@3179.13,2633.27 3249.41,2633.27 3278.54,2662.4 3278.54,2868.11 3243.11,2903.54 v1(3243.11,2914.37)
  Bottom w3.94: v1(2659.45,3274.61) 2665.35,3268.7 2665.35,3125.31 2685.35,3105.31 2798.23,3105.31 2928.15,2975.39 3153.54,2975.39 3219.49,2909.45 3238.19,2909.45 v1(3243.11,2914.37)
MIPI_DPHY1_TX_D1P: U33.183 U90104.11 | length 1239.2
  Top w3.94: U90104.11@2657.48,3336.61 2658.46,3336.61 v1(2658.46,3294.29) ; U33.183@3179.13,2649.02 3199.8,2649.02 3207.09,2641.73 3246.06,2641.73 3270.67,2666.34 3270.67,2864.17 3222.44,2912.4 3222.44,2923.23 v1(3225.39,2923.23)
  Bottom w3.94: v1(2658.46,3294.29) 2662.4,3294.29 2673.23,3283.46 2673.23,3128.57 2688.61,3113.19 2802.17,3113.19 2932.09,2983.27 3157.48,2983.27 3217.52,2923.23 v1(3225.39,2923.23)
MIPI_DPHY1_TX_D2N: U33.193 U90104.16 | length 1227.8
  Top w3.94: v1(2585.63,3277.56) 2598.43,3264.76 U90104.16@2598.43,3223.43 ; v1(3125.98,2901.57) 3119.09,2901.57 3114.17,2896.65 3114.17,2879.92 3155.51,2838.58 3204.72,2838.58 3223.43,2819.88 3223.43,2746.06 3212.6,2735.24 3205.71,2735.24 3198.23,2727.76 U33.193@3179.13,2727.76
  Bottom w3.94: v1@2584.65,3278.54 v1(2585.63,3277.56) 2591.54,3271.65 2591.54,3181.47 2541.34,3131.27 2541.34,3084.65 2567.91,3058.07 2778.66,3058.07 2908.58,2928.15 3071.85,2928.15 3098.43,2901.57 v1(3125.98,2901.57)
MIPI_DPHY1_TX_D2P: U33.195 U90104.17 | length 1211.7
  Top w3.94: v1(2586.61,3297.24) U90104.17@2586.61,3336.61 ; v1(3117.13,2919.29) 3117.13,2912.4 3106.3,2901.57 3106.3,2875.98 3151.57,2830.71 3200.79,2830.71 3215.55,2815.94 3215.55,2750 3209.06,2743.5 U33.195@3179.13,2743.5
  Bottom w3.94: v1(2586.61,3297.24) 2599.41,3284.45 2599.41,3178.21 2549.21,3128.01 2549.21,3087.91 2571.17,3065.94 2781.92,3065.94 2911.84,2936.02 3075.79,2936.02 3102.36,2909.45 3114.17,2909.45 3117.13,2912.4 v1(3117.13,2919.29)
MIPI_DPHY1_TX_D3N: U33.194 U90104.19 | length 1058.4
  Top w3.94: v1(2554.13,3284.45) 2562.99,3293.31 U90104.19@2562.99,3336.61 ; v1(2963.58,2898.62) 2962.6,2899.61 2957.68,2894.68 2957.68,2795.67 3025.59,2727.76 U33.194@3075.2,2727.76
  Bottom w3.94: v1(2554.13,3284.45) 2541.34,3271.65 2541.34,3164.68 2513.78,3137.12 2513.78,3074.19 2553.52,3034.45 2768.87,3034.45 2898.8,2904.53 2957.68,2904.53 v1(2963.58,2898.62)
MIPI_DPHY1_TX_D3P: U33.196 U90104.20 | length 1013
  Top w3.94: U90104.20@2551.18,3223.43 2550.2,3223.43 2550.2,3255.91 v1(2555.12,3260.83) ; v1(2983.27,2898.62) 2965.55,2880.91 2965.55,2798.93 3020.98,2743.5 U33.196@3075.2,2743.5
  Bottom w3.94: v1(2555.12,3260.83) 2549.21,3254.92 2549.21,3161.42 2521.65,3133.86 2521.65,3077.45 2556.78,3042.32 2772.14,3042.32 2902.06,2912.4 2969.49,2912.4 v1(2983.27,2898.62)
N05021: C3.2 J3.4 J3.5 | length 295.1
  Top w19.68: J3.5@2751.39,547.01 2811.23,606.85 C3.2@2811.23,696.61
  Bottom w31.5: J3.4@2701.39,447.01 2701.39,497.01 J3.5@2751.39,547.01
N05653: D4.2 R5.2 R6.2 R8.2 R9.1 | length 161.7
  Top w3.94: R6.2@2218.5,374.02 D4.2@2218.5,332.68 2218.5,335.63 2221.46,332.68 R8.2@2255.91,332.68 ; R9.1@2255.91,295.28 R8.2@2255.91,332.68 ; R5.2@2255.91,374.02 R8.2@2255.91,332.68
N07070: CN14A1.5 ED12.1 R11.2 | length 209.3
  Top w11.81: R11.2@5406.5,655.51 5429.13,678.15 5429.13,698.43 ED12.1@5429.53,698.82 5502.95,698.82 5518.7,683.07 CN14A1.5@5579.5,683.07
N07124: CN14A1.9 ED9.1 R4203.1 R90334.2 | length 3910
  Top w3.94: v1(4464.57,3025.59) 4486.22,3047.24 4557.09,3047.24 4581.69,3071.85 4725.39,3071.85 R90334.2@4742.13,3088.58 R4203.1@4742.13,3122.05 ; v1(4596.46,1108.27) 4816.31,1108.27 4962.6,961.98 4962.6,593.5 5074.8,481.3 5410.83,481.3 ED9.1@5429.53,500
  Top w11.81: ED9.1@5429.53,500 5436.12,506.59 5579.5,506.59 CN14A1.9@5579.5,509.84
  Bottom w3.94: v1(4464.57,3025.59) 4473.48,3025.59 4668.31,2830.77 4668.31,2671.94 4735.24,2605.01 4735.24,1232.65 4610.85,1108.27 v1(4596.46,1108.27)
N28976: C84.1 C87.1 C88.1 L4.2 U17.19
N29602: C89.1 R94.2 R97.2 U17.17 | length 168.6
  Top w9.84: U17.17@3731.49,900.88 3748.03,900.88 3763.49,916.34 C89.1@3806.1,916.34
  Top w11.81: C89.1@3806.1,916.34 R97.2@3806.1,953.74 3806.1,954.79 3805.05,954.79 3837.53,987.27 3838.58,987.27 R94.2@3838.58,986.22
N29722: U17.3 Y1.1 | length 85.2
  Top w3.94: Y1.1@3492.14,927.17 3496.08,927.17 3542.06,881.2 U17.3@3558.26,881.2
N29870: U17.4 Y1.3 | length 194.1
  Top w3.94: Y1.3@3405.52,860.25 3426.84,860.25 3431.11,881.9 3444.88,895.67 3516.26,895.67 3529.53,882.4 3529.53,875.98 3544,861.51 U17.4@3558.26,861.51
N29956: R102.1 U17.13 | length 79.6
  Top w9.84: U17.13@3731.49,822.14 3757.58,822.14 3764.76,814.96 R102.1@3808.07,814.96
N42094: R147.1 U27.8 | length 102
  Top w9.84: U27.8@5382.88,2120.08 5382.87,2113.19 5387.8,2108.27 5437.01,2108.27 R147.1@5464.57,2080.71
N42102: C129.1 R147.2 | length 36.4
  Top w9.84: C129.1@5496.06,2044.29 R147.2@5496.06,2080.71
N42228: C129.2 L12.1 U27.7 | length 830.6
  Top w9.84: 5329.72,2044.29 5329.72,2118.11 5363.19,2151.57 U27.7@5363.19,2135.83 5363.19,2107.28 5375.98,2094.49 5430.12,2094.49 5442.91,2081.69 5442.91,2065.94 C129.2@5464.57,2044.29 5464.57,2023.62 5489.17,1999.02 5489.17,1862.2 5475.39,1848.43 5372.05,1848.43 5371.06,1849.41 5371.06,2002.95 5329.72,2044.29
N42868: R149.1 R152.2 U27.11 | length 108.2
  Top w9.84: U27.11@5420.28,2167.32 5439.96,2167.32 R152.2@5464.57,2191.93 5464.57,2192.39 5464.11,2192.39 5496.52,2224.8 5496.52,2230.84 5496.06,2230.84 R149.1@5496.06,2231.3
